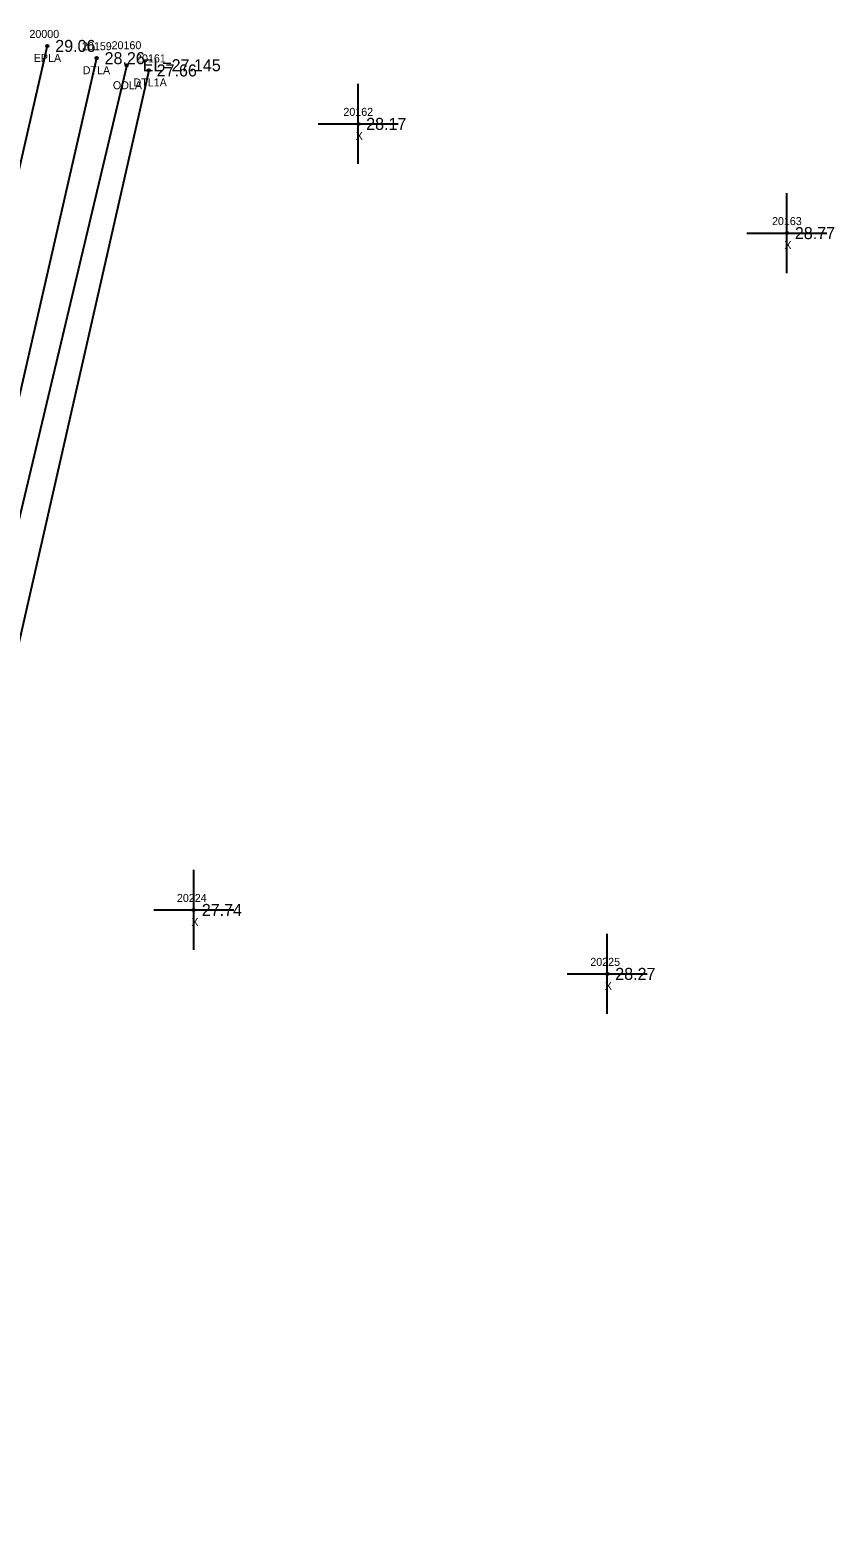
# Model space of a CAD drawing. Extents: x 2655177 to 2656219, y 761780 to 764748.
# Drawn here: x 2656060.7 to 2656161.3, y 764533.5 to 764719.6 of the extents above; entities that cross this region are included whole.
import ezdxf

# ---------------------------------------------------------------- set-up
doc = ezdxf.new("R2010")
doc.units = 0
for name, color, linetype in [('RD_EX_H2O', 7, 'Continuous'), ('RD_EX_H2O_txCode', 7, 'Continuous'), ('RD_EX_Misc', 7, 'Continuous'), ('RD_EX_Misc_txCode', 7, 'Continuous'), ('RD_EX_Road', 7, 'Continuous'), ('RD_EX_Road_txCode', 7, 'Continuous'), ('RD_EX_TX_H2O_ELEV', 7, 'Continuous'), ('RD_EX_TX_Misc_ELEV', 7, 'Continuous'), ('RD_EX_TX_Road_ELEV', 7, 'Continuous'), ('RD_SMD_Locator', 7, 'Continuous')]:
    doc.layers.add(name, color=color, linetype=linetype)

msp = doc.modelspace()

# ---------------------------------------------------------------- linework, layer by layer
at = {"layer": 'RD_EX_H2O'}
for points in [[(2656069.04, 764716.04), (2656046.04, 764615.61), (2656043.09, 764597.03)], [(2656072.8, 764715.16), (2656048.99, 764614.98), (2656045.17, 764598.65)], [(2656075.55, 764714.51), (2656052.69, 764614), (2656046.44, 764596.38), (2656043.09, 764597.03)]]:
    msp.add_lwpolyline(points, dxfattribs=at)
at = {"layer": 'RD_EX_Misc'}
for p, q in [((2656101.74, 764702.83), (2656101.74, 764712.83)), ((2656096.74, 764707.83), (2656106.74, 764707.83)), ((2656155.33, 764689.18), (2656155.33, 764699.18)), ((2656150.33, 764694.18), (2656160.33, 764694.18)), ((2656081.19, 764604.6), (2656081.19, 764614.6)), ((2656076.19, 764609.6), (2656086.19, 764609.6)), ((2656132.88, 764596.61), (2656132.88, 764606.61)), ((2656127.88, 764601.61), (2656137.88, 764601.61))]:
    msp.add_line(p, q, dxfattribs=at)
at = {"layer": 'RD_EX_Road'}
msp.add_lwpolyline([(2656062.87, 764717.57), (2656039.84, 764617.04), (2656035.41, 764597.94), (2656033.38, 764589.18), (2656018.27, 764522.6), (2656017.22, 764517.64), (2656011.07, 764490.22), (2655996.52, 764425.63), (2655974.03, 764327.02), (2655960.71, 764269.34), (2655951.96, 764231.59), (2655930.84, 764138.62), (2655926.81, 764121.01)], dxfattribs=at)
at = {"layer": 'RD_SMD_Locator'}
for centre in [(2656062.87, 764717.57), (2656069.04, 764716.04), (2656072.8, 764715.16), (2656075.55, 764714.51), (2656101.74, 764707.83), (2656155.33, 764694.18), (2656081.19, 764609.6), (2656132.88, 764601.61)]:
    msp.add_circle(centre, 0.15, dxfattribs=at)

# ---------------------------------------------------------------- texts
at = {"layer": 'RD_EX_H2O_txCode'}
for s, p in [('20159', (2656067.21, 764717.04)), ('20160', (2656070.91, 764717.16)), ('20161', (2656073.97, 764715.51)), ('DTLA', (2656067.31, 764714.04)), ('ODLA', (2656071.07, 764712.16)), ('DTL1A', (2656073.65, 764712.51))]:
    msp.add_text(s, height=1, dxfattribs=at).set_placement(p)
at = {"layer": 'RD_EX_Misc_txCode'}
for s, p in [('20162', (2656099.89, 764708.83)), ('X', (2656101.43, 764705.83)), ('20163', (2656153.47, 764695.18)), ('X', (2656155.02, 764692.18)), ('20224', (2656079.08, 764610.6)), ('X', (2656080.88, 764607.6)), ('20225', (2656130.76, 764602.61)), ('X', (2656132.57, 764599.61))]:
    msp.add_text(s, height=1, dxfattribs=at).set_placement(p)
at = {"layer": 'RD_EX_Road_txCode'}
for s, p in [('20000', (2656060.64, 764718.57)), ('EPLA', (2656061.18, 764715.57))]:
    msp.add_text(s, height=1, dxfattribs=at).set_placement(p)
at = {"layer": 'RD_EX_TX_H2O_ELEV'}
for s, p in [('28.26', (2656070.04, 764715.29)), ('EL=27.145', (2656074.8, 764714.41)), ('27.66', (2656076.55, 764713.76))]:
    msp.add_text(s, height=1.5, dxfattribs=at).set_placement(p)
at = {"layer": 'RD_EX_TX_Misc_ELEV'}
for s, p in [('28.17', (2656102.74, 764707.08)), ('28.77', (2656156.33, 764693.43)), ('27.74', (2656082.19, 764608.85)), ('28.27', (2656133.88, 764600.86))]:
    msp.add_text(s, height=1.5, dxfattribs=at).set_placement(p)
at = {"layer": 'RD_EX_TX_Road_ELEV'}
msp.add_text('29.06', height=1.5, dxfattribs=at).set_placement((2656063.87, 764716.82))

doc.saveas('drawing.dxf')
